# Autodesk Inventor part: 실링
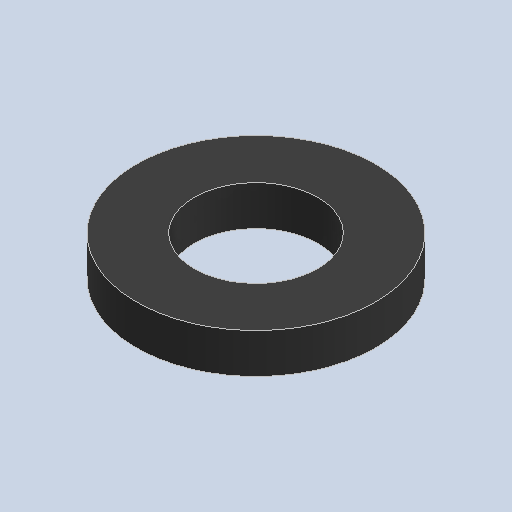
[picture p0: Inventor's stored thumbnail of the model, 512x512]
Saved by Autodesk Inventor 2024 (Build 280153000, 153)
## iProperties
Created: 2025-10
Part Number: 실링
Material: 고무
Document SubType Name: Modeling
Designer: EDU03
Density: 0.93 g/cm^3
Appearance: 기본값
Author: jhkim
Sending System: Autodesk Inventor 2026
Preprocessor: ST-DEVELOPER v20.1
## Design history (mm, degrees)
feature "솔리드1"
node "솔리드2"
